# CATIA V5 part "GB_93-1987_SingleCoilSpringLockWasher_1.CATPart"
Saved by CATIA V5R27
Part number: GB 93-1987 标准型弹簧垫圈_1
Bounding box of the stored display mesh (mm): x -7.7 to 7.7, y -7.69 to 7.699, z 0 to 2.6
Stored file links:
  E:\资料\Catia超级副本\GB 70.1螺钉_带弹垫平垫\GB_93-1987_SingleCoilSpringLockWasher_1.CATPart
  E:\资料\Catia超级副本\GB 93-1987 标准型弹簧垫圈\GB93-87_SingleCoilSpringLockWasher_DesignTable.xlsx
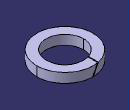
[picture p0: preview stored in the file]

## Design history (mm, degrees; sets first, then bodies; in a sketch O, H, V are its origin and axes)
Parameters
  b = 2.6 mm {design table}
  d = 10.2 mm {design table}
  `公称直径` = 10 mm {design table}
AxisSystem1: origin (0, 0, 0), X (1, 0, 0), Y (0, 1, 0), Z (0, 0, 1)
Set1 "Inputs"
  Plane1: type Normal, Curve Line1, RefPoint Point1, Ratio 0
  Point1: (0, 0, 0), in AxisSystem1
Body1 (main body)
  Set2
    Line1: type PtDir, RefPoint Point1, Direction (0, 0, 1), Start 0, End 20
    Sketch1 on Plane1, origin (0, 0, 0), H (1, 0, 0), V (0, 1, 0)
      circle A1 centre (0, 0) radius 7.7
      circle A2 centre (0, 0) radius 5.1
      radius A1 = 7.7 {= d /2+b}
      radius A2 = 5.1 {= d /2}
      concentricity: A2 A1
    Line2: type PtDir, RefPoint Point1, Direction (1, 0, 0), Start 0, End 20
    Plane2: type 2Lines, Element1 Line2, Element2 Line1
  Pad1: profile Sketch1, direction (0, 0, 1), length 2.6 {= b}
  Sketch2 on Plane2, origin (0, 0, 0), H (1, 0, 0), V (0, 0, 1)
    line L1 (4.9134, -8.7103) -> (5.0866, -8.6103)
    line L2 (5.0866, -8.6103) -> (-4.9134, 8.7103)
    line L3 (-4.9134, 8.7103) -> (-5.0866, 8.6103)
    line L4 (-5.0866, 8.6103) -> (4.9134, -8.7103)
    reference projected point E1 (0, 0) from Point1
    reference projected point E2 (0, 0) from Point1
    distance L2 L4 = 0.2
    distance L4 E1 = 0.1 {= Sketch2.distance(L2 L4) /2}
    angle L4 V = 150
    length L4 = 20
    distance L1 E2 = 10
    parallelism: L1 L3
    perpendicularity: L1 L2
  Pocket1: profile Sketch2, direction (0, 1, 0), through (limit type 3)
Relations
  design table, configuration 8, drives b, d, `公称直径`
